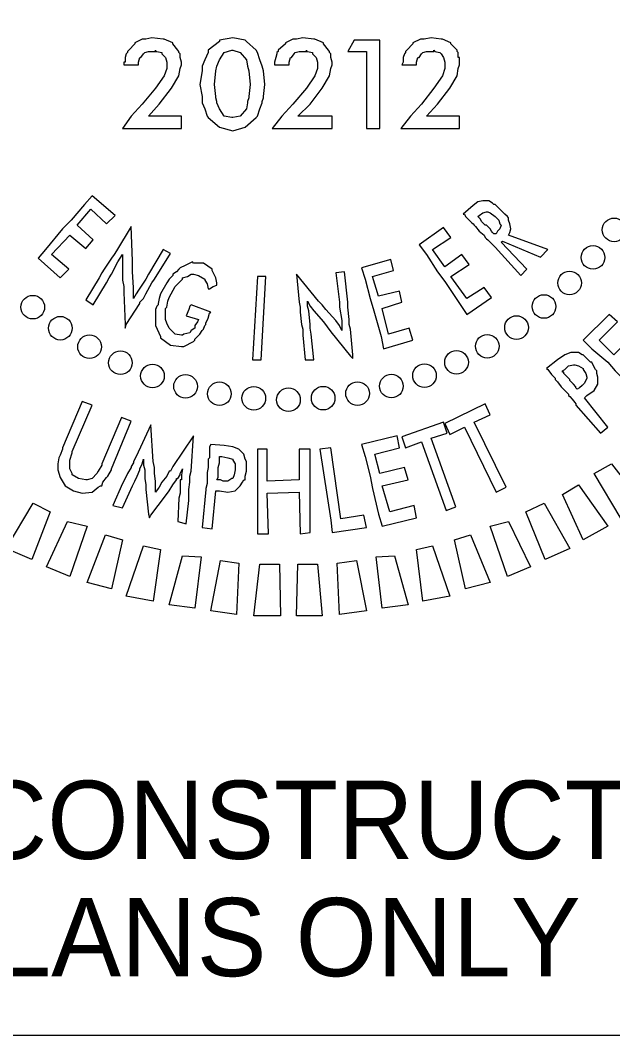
# Model space of a CAD drawing. Extents: x 0 to 2694, y -1 to 1501.
# Drawn here: x 2.6951 to 2.7583, y 1.5677 to 1.6762 of the extents above; entities that cross this region are included whole.
import ezdxf

# ---------------------------------------------------------------- set-up
doc = ezdxf.new("R2010")
doc.units = 0
doc.layers.add('Air Release (M2) CELL', color=7, linetype='Continuous')
doc.layers.add('Diamond Pattern CELL', color=7, linetype='Continuous')

msp = doc.modelspace()

# ---------------------------------------------------------------- linework, layer by layer
at = {"layer": 'Air Release (M2) CELL'}
msp.add_lwpolyline([(2.80496, 1.56775), (2.63979, 1.56775), (2.63979, 1.7556), (2.80496, 1.7556)], dxfattribs=at)
at = {"layer": 'Diamond Pattern CELL'}
for points in [[(2.70735, 1.67364), (2.7067, 1.67298), (2.70657, 1.67285), (2.70657, 1.67272), (2.70644, 1.67259), (2.7063, 1.6722), (2.7063, 1.67168), (2.70617, 1.67168), (2.70617, 1.67141), (2.70774, 1.67141), (2.70774, 1.67168), (2.70787, 1.6722), (2.708, 1.6722), (2.70827, 1.67259), (2.7084, 1.67272), (2.70879, 1.67285), (2.70957, 1.67285), (2.70957, 1.67298), (2.70957, 1.67285), (2.7097, 1.67285), (2.71023, 1.67272), (2.71023, 1.67259), (2.71062, 1.6722), (2.71075, 1.67168), (2.71075, 1.67141), (2.71075, 1.67102), (2.71049, 1.67024), (2.70957, 1.66893), (2.70813, 1.66723), (2.70696, 1.66592), (2.70604, 1.66462), (2.71232, 1.66462), (2.71232, 1.66592), (2.70879, 1.66592), (2.70996, 1.66723), (2.71127, 1.66893), (2.71206, 1.67024), (2.71219, 1.67102), (2.71232, 1.67141), (2.71232, 1.67168), (2.71219, 1.6722), (2.71219, 1.67259), (2.71206, 1.67272), (2.71206, 1.67285), (2.71193, 1.67298), (2.7114, 1.67364), (2.7114, 1.67377), (2.71049, 1.67416), (2.71036, 1.67416), (2.70918, 1.67429), (2.70853, 1.67416), (2.70813, 1.67416), (2.70735, 1.67377), (2.70735, 1.67364), (2.70735, 1.67364)], [(2.72029, 1.67298), (2.71925, 1.6739), (2.71911, 1.67403), (2.71781, 1.67429), (2.71637, 1.67403), (2.71637, 1.6739), (2.71519, 1.67298), (2.71519, 1.67272), (2.7148, 1.67194), (2.71454, 1.67128), (2.71454, 1.67076), (2.71428, 1.66932), (2.71454, 1.66802), (2.71454, 1.66788), (2.71454, 1.66749), (2.71454, 1.66736), (2.7148, 1.66671), (2.71506, 1.66592), (2.71519, 1.66579), (2.71637, 1.66475), (2.71781, 1.66436), (2.71911, 1.66475), (2.72029, 1.66579), (2.72042, 1.66592), (2.72068, 1.66671), (2.72094, 1.66736), (2.72094, 1.66749), (2.72108, 1.66788), (2.72108, 1.66802), (2.72121, 1.66932), (2.72108, 1.67076), (2.72094, 1.67128), (2.72068, 1.67194), (2.72042, 1.67272), (2.72029, 1.67298)], [(2.72343, 1.67364), (2.72264, 1.67298), (2.72264, 1.67285), (2.72251, 1.67272), (2.72251, 1.67259), (2.72238, 1.6722), (2.72225, 1.67168), (2.72225, 1.67141), (2.72382, 1.67141), (2.72382, 1.67168), (2.72395, 1.6722), (2.72408, 1.6722), (2.72434, 1.67259), (2.72447, 1.67272), (2.72487, 1.67285), (2.72565, 1.67285), (2.72565, 1.67298), (2.72565, 1.67285), (2.72578, 1.67285), (2.7263, 1.67272), (2.7263, 1.67259), (2.7267, 1.6722), (2.72683, 1.67168), (2.72683, 1.67141), (2.72683, 1.67102), (2.72656, 1.67024), (2.72565, 1.66893), (2.72421, 1.66723), (2.72304, 1.66592), (2.72199, 1.66462), (2.72839, 1.66462), (2.72839, 1.66592), (2.72473, 1.66592), (2.72604, 1.66723), (2.72735, 1.66893), (2.72813, 1.67024), (2.72826, 1.67102), (2.72839, 1.67141), (2.72839, 1.67168), (2.72826, 1.6722), (2.72826, 1.67259), (2.72813, 1.67272), (2.72813, 1.67285), (2.728, 1.67298), (2.72748, 1.67364), (2.72748, 1.67377), (2.72656, 1.67416), (2.72643, 1.67416), (2.72526, 1.67429), (2.7246, 1.67416), (2.72421, 1.67416), (2.72343, 1.67377), (2.72343, 1.67364), (2.72343, 1.67364)], [(2.73205, 1.67285), (2.73205, 1.66462), (2.73349, 1.66462), (2.73349, 1.67403), (2.73075, 1.67403), (2.73009, 1.67285), (2.73205, 1.67285), (2.73205, 1.67285)], [(2.73702, 1.67364), (2.73637, 1.67298), (2.73624, 1.67285), (2.73624, 1.67272), (2.73611, 1.67259), (2.73598, 1.6722), (2.73598, 1.67168), (2.73585, 1.67141), (2.73741, 1.67141), (2.73741, 1.67168), (2.73754, 1.6722), (2.73768, 1.6722), (2.73794, 1.67259), (2.73807, 1.67272), (2.73846, 1.67285), (2.73924, 1.67285), (2.73924, 1.67298), (2.73937, 1.67285), (2.7399, 1.67272), (2.74003, 1.67259), (2.74029, 1.6722), (2.74042, 1.67168), (2.74042, 1.67141), (2.74042, 1.67102), (2.74016, 1.67024), (2.73924, 1.66893), (2.73794, 1.66723), (2.73676, 1.66592), (2.73571, 1.66462), (2.74199, 1.66462), (2.74199, 1.66592), (2.73846, 1.66592), (2.73964, 1.66723), (2.74094, 1.66893), (2.74173, 1.67024), (2.74186, 1.67102), (2.74199, 1.67141), (2.74199, 1.67168), (2.74199, 1.6722), (2.74186, 1.6722), (2.74186, 1.67259), (2.74186, 1.67272), (2.74173, 1.67285), (2.74173, 1.67298), (2.74107, 1.67364), (2.74107, 1.67377), (2.74016, 1.67416), (2.74003, 1.67416), (2.73898, 1.67429), (2.7382, 1.67416), (2.73781, 1.67416), (2.73702, 1.67377), (2.73702, 1.67364), (2.73702, 1.67364)], [(2.71964, 1.66932), (2.71951, 1.66802), (2.71951, 1.66788), (2.71938, 1.66749), (2.71938, 1.66736), (2.71925, 1.66671), (2.71859, 1.66592), (2.71781, 1.66579), (2.71768, 1.66579), (2.71689, 1.66592), (2.71637, 1.66671), (2.71611, 1.66736), (2.71611, 1.66749), (2.71598, 1.66788), (2.71598, 1.66802), (2.71585, 1.66932), (2.71598, 1.67076), (2.71611, 1.67128), (2.71637, 1.67194), (2.71689, 1.67272), (2.71768, 1.67298), (2.71781, 1.67298), (2.71859, 1.67272), (2.71925, 1.67194), (2.71938, 1.67128), (2.71951, 1.67076), (2.71964, 1.66932), (2.71964, 1.66932)], [(2.69781, 1.65168), (2.69702, 1.65076), (2.69938, 1.64867), (2.70029, 1.64959), (2.69846, 1.65115), (2.70042, 1.65324), (2.70212, 1.65181), (2.70291, 1.65272), (2.70121, 1.65429), (2.70264, 1.65599), (2.70434, 1.65442), (2.70526, 1.65534), (2.70278, 1.65743), (2.70199, 1.65651), (2.70055, 1.65481), (2.69964, 1.6539), (2.69781, 1.65168), (2.69781, 1.65168)], [(2.74552, 1.65664), (2.74513, 1.6569), (2.74447, 1.6569), (2.74395, 1.65677), (2.74343, 1.65638), (2.74238, 1.65547), (2.74251, 1.65547), (2.74264, 1.65521), (2.74303, 1.65481), (2.7433, 1.65455), (2.74343, 1.65442), (2.74356, 1.65429), (2.74369, 1.65416), (2.74408, 1.65364), (2.7446, 1.65324), (2.74473, 1.65298), (2.74486, 1.65285), (2.745, 1.65272), (2.74526, 1.65246), (2.74565, 1.65207), (2.74578, 1.65194), (2.74852, 1.64893), (2.74918, 1.64959), (2.74643, 1.65246), (2.74656, 1.65259), (2.75062, 1.65089), (2.7514, 1.65168), (2.74722, 1.65324), (2.74735, 1.65351), (2.74748, 1.6539), (2.74735, 1.65442), (2.74722, 1.65481), (2.74722, 1.65494), (2.74722, 1.65507), (2.74709, 1.65521), (2.74683, 1.65547), (2.74643, 1.65586), (2.74604, 1.65625), (2.74578, 1.65651), (2.74565, 1.65651), (2.74552, 1.65664)], [(2.74408, 1.65534), (2.74447, 1.6556), (2.74486, 1.65573), (2.745, 1.65573), (2.74526, 1.6556), (2.74578, 1.65521), (2.74617, 1.65481), (2.7463, 1.65442), (2.74643, 1.65429), (2.7463, 1.6539), (2.74604, 1.65364), (2.74591, 1.65338), (2.74578, 1.65338), (2.74565, 1.65338), (2.74552, 1.65351), (2.74539, 1.65364), (2.74526, 1.6539), (2.74486, 1.65429), (2.74473, 1.65429), (2.74434, 1.65468), (2.74421, 1.65494), (2.74408, 1.65507), (2.74395, 1.65521), (2.74408, 1.65534), (2.74408, 1.65534)], [(2.70722, 1.64645), (2.70722, 1.64762), (2.70709, 1.64932), (2.70709, 1.64998), (2.70709, 1.6505), (2.70696, 1.65416), (2.70539, 1.65155), (2.70513, 1.65115), (2.70487, 1.65076), (2.70408, 1.64959), (2.70382, 1.64919), (2.70356, 1.64867), (2.70212, 1.64632), (2.70291, 1.64579), (2.70434, 1.64815), (2.70461, 1.64867), (2.70487, 1.64906), (2.70552, 1.65037), (2.70578, 1.65076), (2.70604, 1.65115), (2.70604, 1.65063), (2.70604, 1.64998), (2.70604, 1.64841), (2.70617, 1.64776), (2.70617, 1.6471), (2.7063, 1.6437), (2.7063, 1.64331), (2.70644, 1.6437), (2.70787, 1.64593), (2.70787, 1.64606), (2.70827, 1.64645), (2.70853, 1.64697), (2.70918, 1.64815), (2.70944, 1.64854), (2.71114, 1.65128), (2.71036, 1.65168), (2.70879, 1.64906), (2.70853, 1.64854), (2.70774, 1.64736), (2.70748, 1.64697), (2.70722, 1.64645), (2.70722, 1.64645)], [(2.74199, 1.64593), (2.74277, 1.64475), (2.74539, 1.64658), (2.7446, 1.64762), (2.74277, 1.64645), (2.74107, 1.6488), (2.74303, 1.65011), (2.74225, 1.65115), (2.74042, 1.64985), (2.73911, 1.65168), (2.74107, 1.65298), (2.74029, 1.65403), (2.73768, 1.6522), (2.73846, 1.65115), (2.73964, 1.64932), (2.74042, 1.64828), (2.74199, 1.64593), (2.74199, 1.64593)], [(2.71611, 1.64815), (2.71598, 1.64867), (2.71559, 1.64945), (2.71559, 1.64959), (2.71467, 1.65024), (2.71362, 1.65024), (2.71349, 1.65037), (2.71271, 1.64998), (2.71219, 1.64972), (2.71206, 1.64959), (2.71179, 1.64932), (2.7114, 1.64906), (2.7114, 1.64893), (2.71101, 1.64854), (2.71075, 1.64815), (2.7101, 1.64697), (2.70996, 1.64645), (2.70983, 1.64593), (2.70983, 1.64579), (2.7097, 1.64566), (2.70957, 1.64527), (2.70957, 1.64514), (2.70957, 1.64501), (2.70957, 1.64462), (2.70957, 1.64423), (2.70957, 1.64383), (2.70957, 1.6437), (2.70957, 1.64357), (2.7101, 1.6424), (2.7101, 1.64227), (2.71114, 1.64148), (2.71232, 1.64135), (2.71258, 1.64135), (2.71362, 1.64187), (2.71376, 1.642), (2.71376, 1.64213), (2.71402, 1.6424), (2.71428, 1.64266), (2.71454, 1.64305), (2.71467, 1.64318), (2.7148, 1.64357), (2.71493, 1.6437), (2.71493, 1.64383), (2.71519, 1.64436), (2.71532, 1.64488), (2.71545, 1.64501), (2.71336, 1.64579), (2.71323, 1.64566), (2.7131, 1.64527), (2.71284, 1.64462), (2.71415, 1.64423), (2.71402, 1.64396), (2.71376, 1.64357), (2.71376, 1.64344), (2.71376, 1.64331), (2.71336, 1.64305), (2.71323, 1.64279), (2.71258, 1.64266), (2.71245, 1.64253), (2.71232, 1.64253), (2.71166, 1.64266), (2.71127, 1.64305), (2.71101, 1.64331), (2.71075, 1.64383), (2.71062, 1.64423), (2.71062, 1.64462), (2.71062, 1.64475), (2.71062, 1.64527), (2.71062, 1.6454), (2.71075, 1.64553), (2.71088, 1.64619), (2.71101, 1.64658), (2.71166, 1.64776), (2.71206, 1.64815), (2.71245, 1.64854), (2.71245, 1.64867), (2.71297, 1.6488), (2.71336, 1.64906), (2.71362, 1.64906), (2.71415, 1.64893), (2.7148, 1.64854), (2.7148, 1.64841), (2.71506, 1.64802), (2.71519, 1.64749), (2.71532, 1.64749), (2.71572, 1.64776), (2.71611, 1.64789), (2.71611, 1.64802), (2.71611, 1.64815), (2.71611, 1.64815)], [(2.73362, 1.6424), (2.73388, 1.64109), (2.73702, 1.642), (2.73663, 1.64331), (2.73441, 1.64266), (2.73375, 1.6454), (2.73585, 1.64606), (2.73558, 1.64723), (2.73336, 1.64671), (2.73271, 1.6488), (2.73493, 1.64945), (2.73467, 1.65063), (2.73153, 1.64972), (2.73192, 1.64854), (2.73245, 1.64645), (2.73284, 1.64514), (2.73362, 1.6424), (2.73362, 1.6424)], [(2.72944, 1.64305), (2.72918, 1.64357), (2.72879, 1.6441), (2.72774, 1.64527), (2.72735, 1.64579), (2.72696, 1.64619), (2.7246, 1.64906), (2.72487, 1.64606), (2.725, 1.64553), (2.725, 1.64501), (2.72513, 1.6437), (2.72526, 1.64318), (2.72526, 1.64253), (2.72552, 1.63991), (2.72643, 1.63991), (2.72617, 1.64266), (2.72604, 1.64331), (2.72604, 1.6437), (2.72591, 1.64514), (2.72578, 1.64566), (2.72578, 1.64606), (2.72578, 1.64619), (2.72604, 1.64566), (2.72643, 1.64514), (2.72748, 1.64396), (2.72787, 1.64344), (2.72826, 1.64292), (2.73036, 1.6403), (2.73062, 1.64004), (2.73062, 1.64044), (2.73036, 1.64318), (2.73022, 1.6437), (2.73022, 1.64423), (2.73009, 1.64553), (2.73009, 1.64606), (2.7297, 1.64932), (2.72879, 1.64919), (2.72918, 1.64606), (2.72918, 1.64553), (2.72944, 1.6441), (2.72944, 1.64357), (2.72944, 1.64305), (2.72944, 1.64305)], [(2.76068, 1.63664), (2.7616, 1.63573), (2.76434, 1.63847), (2.76343, 1.63939), (2.76146, 1.63743), (2.75937, 1.63952), (2.76133, 1.64148), (2.76042, 1.6424), (2.75846, 1.64044), (2.75689, 1.642), (2.75885, 1.64396), (2.75794, 1.64475), (2.75519, 1.642), (2.75611, 1.64109), (2.7578, 1.63965), (2.75859, 1.63874), (2.76068, 1.63664), (2.76068, 1.63664)], [(2.75506, 1.64044), (2.75467, 1.6407), (2.75388, 1.6407), (2.75323, 1.64044), (2.75245, 1.63991), (2.75127, 1.639), (2.7514, 1.63887), (2.75153, 1.63874), (2.75179, 1.63834), (2.75218, 1.63795), (2.75218, 1.63782), (2.75231, 1.63769), (2.75245, 1.63756), (2.75284, 1.63704), (2.75323, 1.63664), (2.75349, 1.63638), (2.75362, 1.63625), (2.75362, 1.63612), (2.75375, 1.63599), (2.75401, 1.63573), (2.75428, 1.63534), (2.75441, 1.63521), (2.75441, 1.63508), (2.75702, 1.63207), (2.7578, 1.63272), (2.75532, 1.63586), (2.75558, 1.63612), (2.75637, 1.63664), (2.75676, 1.6373), (2.75676, 1.63808), (2.75663, 1.63847), (2.75663, 1.63861), (2.75663, 1.63874), (2.7565, 1.63887), (2.75637, 1.63913), (2.75611, 1.63965), (2.75597, 1.63965), (2.75558, 1.64004), (2.75532, 1.6403), (2.75519, 1.64044), (2.75506, 1.64044), (2.75506, 1.64044)], [(2.75558, 1.63795), (2.75532, 1.63743), (2.75506, 1.63717), (2.7548, 1.63691), (2.75454, 1.63678), (2.75441, 1.63691), (2.75441, 1.63704), (2.75414, 1.6373), (2.75375, 1.63769), (2.75375, 1.63782), (2.75336, 1.63821), (2.7531, 1.63847), (2.7531, 1.63861), (2.75297, 1.63861), (2.75297, 1.63874), (2.75323, 1.63887), (2.75362, 1.63926), (2.75414, 1.63939), (2.75428, 1.63939), (2.75467, 1.63926), (2.75519, 1.639), (2.75519, 1.63887), (2.75545, 1.63847), (2.75558, 1.63808), (2.75558, 1.63795), (2.75558, 1.63795)], [(2.70134, 1.62723), (2.70068, 1.62763), (2.70068, 1.62776), (2.70042, 1.62828), (2.70042, 1.62906), (2.70042, 1.62919), (2.70068, 1.62998), (2.70068, 1.63011), (2.70278, 1.63508), (2.70173, 1.63547), (2.69964, 1.6305), (2.69964, 1.63037), (2.69938, 1.62972), (2.69925, 1.62946), (2.69912, 1.6288), (2.69912, 1.62841), (2.69912, 1.62828), (2.69912, 1.62815), (2.69938, 1.62736), (2.6999, 1.62645), (2.70081, 1.62593), (2.70173, 1.62567), (2.70278, 1.6258), (2.70343, 1.62632), (2.70369, 1.62645), (2.70382, 1.62645), (2.70395, 1.62684), (2.70434, 1.62736), (2.70447, 1.6275), (2.70487, 1.62815), (2.70487, 1.62828), (2.70696, 1.63338), (2.70591, 1.63377), (2.70382, 1.6288), (2.70382, 1.62867), (2.70343, 1.62802), (2.7033, 1.62776), (2.70278, 1.62723), (2.70225, 1.6271), (2.70212, 1.6271), (2.70134, 1.62723), (2.70134, 1.62723)], [(2.74251, 1.63272), (2.74591, 1.6258), (2.74696, 1.62632), (2.74356, 1.63325), (2.74526, 1.63403), (2.74473, 1.63521), (2.74042, 1.63312), (2.74094, 1.63194), (2.74251, 1.63272), (2.74251, 1.63272)], [(2.70957, 1.6258), (2.70957, 1.62697), (2.70944, 1.62776), (2.70944, 1.62789), (2.70944, 1.62841), (2.70931, 1.62906), (2.70905, 1.63298), (2.70748, 1.62959), (2.70722, 1.62906), (2.70722, 1.62893), (2.70696, 1.62854), (2.70696, 1.62841), (2.70657, 1.62776), (2.7063, 1.62723), (2.70604, 1.62671), (2.705, 1.62436), (2.70604, 1.6241), (2.70709, 1.62645), (2.70735, 1.62697), (2.70761, 1.6275), (2.70787, 1.62815), (2.70787, 1.62828), (2.70813, 1.6288), (2.70827, 1.62932), (2.70827, 1.6288), (2.70827, 1.62867), (2.7084, 1.62815), (2.7084, 1.62802), (2.7084, 1.62723), (2.70853, 1.62658), (2.70853, 1.62606), (2.70879, 1.62344), (2.70892, 1.62305), (2.70905, 1.62331), (2.71062, 1.6254), (2.71101, 1.62593), (2.7114, 1.62658), (2.71179, 1.6271), (2.71179, 1.62723), (2.71193, 1.62723), (2.71219, 1.62763), (2.71219, 1.62776), (2.71245, 1.62828), (2.71232, 1.62763), (2.71232, 1.6271), (2.71219, 1.6271), (2.71219, 1.62632), (2.71219, 1.62567), (2.71206, 1.62514), (2.71193, 1.62266), (2.71284, 1.6224), (2.7131, 1.62488), (2.7131, 1.6254), (2.7131, 1.62606), (2.71323, 1.62684), (2.71323, 1.62736), (2.71323, 1.6275), (2.71336, 1.62802), (2.71362, 1.63181), (2.7114, 1.62854), (2.71114, 1.62802), (2.71101, 1.62802), (2.71075, 1.6275), (2.71023, 1.62684), (2.70996, 1.62632), (2.70983, 1.62619), (2.70957, 1.6258), (2.70957, 1.6258)], [(2.73794, 1.63115), (2.74055, 1.62384), (2.7416, 1.62423), (2.73898, 1.63155), (2.74068, 1.63207), (2.74029, 1.63325), (2.73585, 1.63168), (2.73624, 1.6305), (2.73794, 1.63115), (2.73794, 1.63115)], [(2.73336, 1.62344), (2.73375, 1.62214), (2.73741, 1.62305), (2.73715, 1.62436), (2.73454, 1.6237), (2.73375, 1.62645), (2.7365, 1.6271), (2.73611, 1.62841), (2.73349, 1.62776), (2.73297, 1.62985), (2.73558, 1.6305), (2.73532, 1.63181), (2.73153, 1.63089), (2.73192, 1.62959), (2.73245, 1.6275), (2.73271, 1.62619), (2.73336, 1.62344), (2.73336, 1.62344)], [(2.71911, 1.62932), (2.71898, 1.62985), (2.71846, 1.63037), (2.71781, 1.63063), (2.71689, 1.63076), (2.71545, 1.63089), (2.71532, 1.63063), (2.71532, 1.63011), (2.71532, 1.62972), (2.71532, 1.62959), (2.71532, 1.62946), (2.71519, 1.62932), (2.71519, 1.62906), (2.71519, 1.62854), (2.71519, 1.62841), (2.71506, 1.62789), (2.71506, 1.6275), (2.71506, 1.62723), (2.71506, 1.62671), (2.71493, 1.62619), (2.71493, 1.62606), (2.71454, 1.62201), (2.71559, 1.62187), (2.71598, 1.62593), (2.71637, 1.62593), (2.71728, 1.6258), (2.71807, 1.62593), (2.71859, 1.62645), (2.71885, 1.62684), (2.71898, 1.6271), (2.71911, 1.6271), (2.71911, 1.6275), (2.71925, 1.62802), (2.71925, 1.62815), (2.71925, 1.62867), (2.71925, 1.62906), (2.71911, 1.62932), (2.71911, 1.62932)], [(2.71768, 1.62723), (2.71728, 1.62697), (2.71676, 1.62697), (2.7165, 1.6271), (2.71611, 1.6271), (2.71624, 1.62736), (2.71624, 1.6275), (2.71624, 1.62776), (2.71624, 1.62841), (2.71637, 1.62893), (2.71637, 1.62932), (2.71637, 1.62946), (2.71637, 1.62959), (2.71663, 1.62959), (2.71728, 1.62946), (2.71781, 1.62932), (2.71781, 1.62919), (2.71807, 1.6288), (2.71807, 1.62828), (2.71807, 1.62815), (2.71794, 1.62763), (2.71781, 1.62723), (2.71768, 1.62723), (2.71768, 1.62723)], [(2.72487, 1.6271), (2.72147, 1.62697), (2.72147, 1.63037), (2.72042, 1.63037), (2.72042, 1.62697), (2.72042, 1.62567), (2.72042, 1.62135), (2.7216, 1.62135), (2.72147, 1.62567), (2.72487, 1.6258), (2.725, 1.62135), (2.72604, 1.62148), (2.72604, 1.6258), (2.72604, 1.6271), (2.72604, 1.63037), (2.72487, 1.63037), (2.72487, 1.6271), (2.72487, 1.6271)], [(2.72826, 1.62279), (2.72839, 1.62148), (2.73205, 1.62201), (2.73179, 1.62331), (2.72931, 1.62292), (2.72826, 1.6305), (2.72709, 1.63037), (2.72826, 1.62279), (2.72826, 1.62279)]]:
    msp.add_lwpolyline(points, dxfattribs=at)
for points in [[(2.72042, 1.6488), (2.7199, 1.63991), (2.72081, 1.63991), (2.72134, 1.6488)], [(2.7582, 1.6288), (2.76146, 1.62462), (2.75924, 1.62292), (2.75637, 1.62776)], [(2.75467, 1.62658), (2.7578, 1.62214), (2.75519, 1.6207), (2.75297, 1.62553)], [(2.69833, 1.6237), (2.69637, 1.61861), (2.69363, 1.61978), (2.6965, 1.62462)], [(2.75101, 1.62462), (2.75375, 1.61978), (2.75114, 1.61861), (2.74905, 1.6237)], [(2.70225, 1.62214), (2.70042, 1.61678), (2.69794, 1.61782), (2.70016, 1.62266)], [(2.74722, 1.62266), (2.74957, 1.61782), (2.74709, 1.61678), (2.74526, 1.62214)], [(2.70604, 1.6207), (2.70487, 1.61547), (2.70225, 1.61612), (2.70421, 1.62122)], [(2.74317, 1.62122), (2.74526, 1.61612), (2.74264, 1.61547), (2.74147, 1.6207)], [(2.7101, 1.61965), (2.70931, 1.61416), (2.70644, 1.61469), (2.70827, 1.62004)], [(2.73911, 1.62004), (2.74094, 1.61469), (2.73807, 1.61416), (2.73741, 1.61965)], [(2.71441, 1.61887), (2.71376, 1.61338), (2.71101, 1.61377), (2.71245, 1.619)], [(2.73506, 1.619), (2.7365, 1.61377), (2.73375, 1.61338), (2.7331, 1.61887)], [(2.71846, 1.61821), (2.7182, 1.61272), (2.71545, 1.61312), (2.7165, 1.61848)], [(2.72277, 1.61808), (2.7229, 1.61259), (2.72003, 1.61259), (2.72068, 1.61808)], [(2.72683, 1.61808), (2.72735, 1.61259), (2.7246, 1.61259), (2.72473, 1.61808)], [(2.73101, 1.61848), (2.73205, 1.61312), (2.72918, 1.61272), (2.72892, 1.61821)]]:
    msp.add_lwpolyline(points, close=True, dxfattribs=at)
for centre in [(2.75848, 1.65379), (2.75623, 1.65085), (2.75373, 1.64812), (2.69646, 1.64554), (2.751, 1.64561), (2.6994, 1.64329), (2.74807, 1.64336), (2.74495, 1.64136), (2.70252, 1.64131), (2.70581, 1.6396), (2.74167, 1.63965), (2.70923, 1.63819), (2.73825, 1.63823), (2.71276, 1.63708), (2.73472, 1.63711), (2.71637, 1.63629), (2.73111, 1.63631), (2.72004, 1.63581), (2.72374, 1.63565), (2.72744, 1.63582)]:
    msp.add_circle(centre, 0.00126, dxfattribs=at)

# ---------------------------------------------------------------- texts
at = {"layer": 'Air Release (M2) CELL'}
for s, height, p in [('UTILITY CONSTRUCTION', 0.0083524, (2.64525, 1.58662)), ('PLANS ONLY', 0.008352, (2.68477, 1.5741))]:
    msp.add_text(s, height=height, dxfattribs=at).set_placement(p)

doc.saveas('drawing.dxf')
